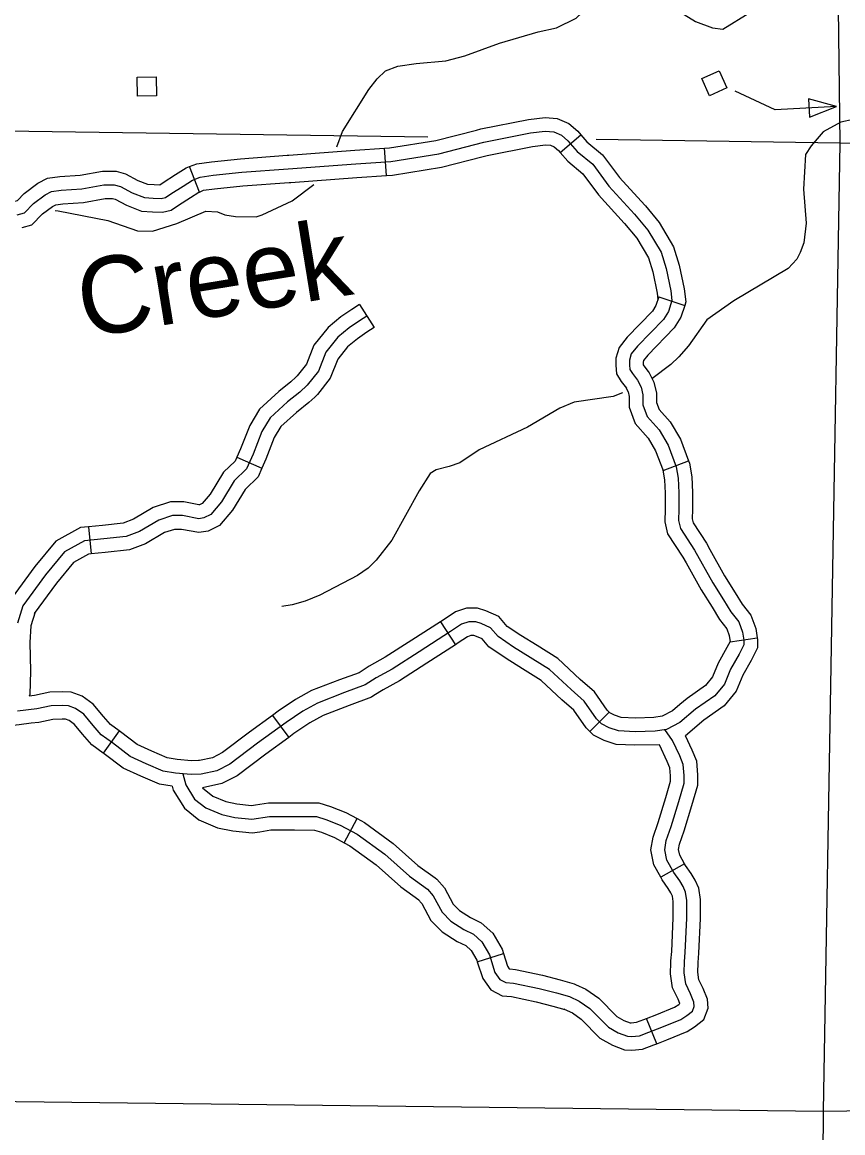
# Model space of a CAD drawing. Extents: x -19 to 366, y -4 to 359.
# Drawn here: x 137.551 to 138.405, y 195.99 to 197.146 of the extents above; entities that cross this region are included whole.
import ezdxf

# ---------------------------------------------------------------- set-up
doc = ezdxf.new("R2010")
doc.units = 0
for name, color, linetype in [('Level 35', 7, 'Continuous'), ('Level 45', 7, 'Continuous'), ('Level 5', 7, 'Continuous'), ('Level 56', 7, 'Continuous'), ('Level 60', 7, 'Continuous')]:
    doc.layers.add(name, color=color, linetype=linetype)

msp = doc.modelspace()

# ---------------------------------------------------------------- linework, layer by layer
at = {"layer": 'Level 35'}
for points in [[(137.8788, 197.0161), (137.8845, 197.0319), (137.9119, 197.0756), (137.9205, 197.0867), (137.9292, 197.095), (137.942, 197.1), (137.9613, 197.1027), (137.9919, 197.1055), (138.0119, 197.1105), (138.0478, 197.1239), (138.0882, 197.1355), (138.1071, 197.1397), (138.1275, 197.1497), (138.1399, 197.1611), (138.1452, 197.1691), (138.1534, 197.1759), (138.1716, 197.1828), (138.184, 197.184), (138.1931, 197.1814), (138.2071, 197.1746)], [(138.2071, 197.1746), (138.2253, 197.1641), (138.2401, 197.1535), (138.2519, 197.1463), (138.2693, 197.1396), (138.2803, 197.1385), (138.3084, 197.1558), (138.3345, 197.1823)], [(138.4157, 197.0444), (138.4029, 197.0416), (138.3846, 197.0314), (138.372, 197.0171), (138.3661, 197.0079), (138.3641, 196.9718), (138.367, 196.9366), (138.3643, 196.9161), (138.3607, 196.9061), (138.3571, 196.8992), (138.3482, 196.8892)], [(137.5857, 196.9496), (137.5887, 196.9492), (137.6406, 196.9392), (137.6713, 196.9286), (137.6871, 196.9283), (137.7124, 196.936), (137.7423, 196.949), (137.7544, 196.9483), (137.7623, 196.9453), (137.7733, 196.9435), (137.7948, 196.9432), (137.8009, 196.9451), (137.8322, 196.9596), (137.8546, 196.9767)], [(138.3482, 196.8892), (138.2918, 196.8558), (138.2636, 196.8358), (138.2445, 196.809), (138.2346, 196.7973), (138.2262, 196.7893), (138.2065, 196.7747)], [(138.1757, 196.7601), (138.1661, 196.756), (138.1254, 196.7503), (138.1108, 196.744), (138.0771, 196.7241), (138.0269, 196.7008), (138.0067, 196.6872), (137.9955, 196.6832), (137.9819, 196.68), (137.9756, 196.6761), (137.9645, 196.658), (137.936, 196.6067), (137.9197, 196.5859), (137.9112, 196.5774), (137.9003, 196.57), (137.861, 196.5496), (137.8456, 196.5433), (137.8321, 196.5393), (137.8216, 196.5376)]]:
    msp.add_lwpolyline(points, dxfattribs=at)
at = {"layer": 'Level 45'}
for p, q in [((138.111, 197.0099), (138.1326, 197.0284)), ((137.9303, 196.9861), (137.9284, 197.0145)), ((137.7357, 196.9689), (137.7253, 196.9954)), ((138.2135, 196.8597), (138.2405, 196.851)), ((137.9022, 196.8518), (137.9176, 196.8279)), ((137.7748, 196.6932), (137.8007, 196.6817)), ((138.218, 196.6791), (138.2446, 196.6891)), ((137.6205, 196.6207), (137.6231, 196.5924)), ((137.9866, 196.5217), (138.002, 196.4978)), ((138.2878, 196.5009), (138.3159, 196.5049)), ((137.8119, 196.4244), (137.8287, 196.4015)), ((138.162, 196.4276), (138.1419, 196.4075)), ((137.6522, 196.4082), (137.6355, 196.3852)), ((137.8863, 196.2919), (137.8999, 196.3169)), ((138.2404, 196.2699), (138.2156, 196.2561)), ((138.0248, 196.1679), (138.0519, 196.1765)), ((138.2116, 196.0827), (138.2009, 196.109))]:
    msp.add_line(p, q, dxfattribs=at)
for points in [[(138.0238, 197.0333), (138.0285, 197.0345), (138.0779, 197.0445), (138.0953, 197.0465), (138.1078, 197.0455), (138.1199, 197.0402), (138.1292, 197.0324), (138.1326, 197.0284)], [(137.9284, 197.0145), (137.9333, 197.0148), (137.9818, 197.0226), (138.0238, 197.0333)], [(137.5462, 196.9452), (137.5539, 196.9474), (137.563, 196.9568), (137.5753, 196.9659), (137.582, 196.9694), (137.5921, 196.9708), (137.6135, 196.9723), (137.6363, 196.9765), (137.6472, 196.9765), (137.6535, 196.9747), (137.6658, 196.968), (137.6787, 196.9631), (137.6878, 196.9624), (137.6959, 196.9621), (137.7005, 196.9631), (137.7061, 196.967), (137.7187, 196.9751), (137.7285, 196.9814), (137.7366, 196.9845), (137.7499, 196.9863), (137.7797, 196.9894), (137.828, 196.9929), (137.8985, 196.9982), (137.935, 197.0007), (137.9847, 197.0087), (138.0317, 197.0207), (138.0801, 197.0305), (138.0955, 197.0322), (138.1043, 197.0315), (138.1123, 197.028), (138.1191, 197.0223), (138.1288, 197.0111), (138.1449, 196.9978), (138.1617, 196.9749), (138.1882, 196.946), (138.2023, 196.9291), (138.2159, 196.9062), (138.2212, 196.8893), (138.226, 196.866), (138.2272, 196.8559), (138.2236, 196.8447), (138.2184, 196.8362), (138.1914, 196.8085), (138.185, 196.8005), (138.183, 196.794), (138.183, 196.7892)], [(138.1326, 197.0284), (138.1388, 197.0212), (138.1552, 197.0076), (138.1727, 196.9839), (138.1989, 196.9553), (138.1997, 196.9544)], [(137.8286, 197.0072), (137.8975, 197.0124), (137.9284, 197.0145)], [(138.0308, 197.0058), (138.0349, 197.0068), (138.0823, 197.0164), (138.0957, 197.018), (138.1008, 197.0176), (138.1048, 197.0158), (138.1091, 197.0122), (138.111, 197.0099)], [(138.111, 197.0099), (138.1188, 197.0009), (138.1345, 196.988), (138.1507, 196.9659), (138.1775, 196.9366), (138.1778, 196.9363)], [(137.7253, 196.9954), (137.733, 196.9984), (137.7482, 197.0004), (137.7784, 197.0036), (137.827, 197.0071), (137.8286, 197.0072)], [(137.9303, 196.9861), (137.9366, 196.9865), (137.9876, 196.9948), (138.0308, 197.0058)], [(137.5439, 196.9593), (137.5464, 196.96), (137.5536, 196.9675), (137.5677, 196.978), (137.5776, 196.9832), (137.5907, 196.985), (137.6118, 196.9864), (137.635, 196.9907), (137.639, 196.9907)], [(137.639, 196.9907), (137.6491, 196.9907), (137.6588, 196.988), (137.6717, 196.981), (137.6818, 196.9771), (137.6887, 196.9766), (137.6946, 196.9764), (137.6946, 196.9764), (137.6982, 196.9788), (137.711, 196.987), (137.722, 196.9941), (137.7253, 196.9954)], [(137.7357, 196.9689), (137.7401, 196.9707), (137.7516, 196.9722), (137.7809, 196.9753), (137.8291, 196.9788), (137.8307, 196.9789)], [(137.8307, 196.9789), (137.8995, 196.984), (137.9303, 196.9861)], [(137.639, 196.9623), (137.6452, 196.9623), (137.6481, 196.9615), (137.6598, 196.9551), (137.6756, 196.9491), (137.687, 196.9483), (137.6972, 196.9478), (137.7063, 196.9499), (137.7139, 196.9552), (137.7264, 196.9631), (137.735, 196.9687), (137.7357, 196.9689)], [(137.5514, 196.9319), (137.5615, 196.9347), (137.5725, 196.9461), (137.5829, 196.9539), (137.5864, 196.9557), (137.5936, 196.9567), (137.6153, 196.9581), (137.6376, 196.9623), (137.639, 196.9623)], [(138.1997, 196.9544), (138.2139, 196.9373), (138.229, 196.912), (138.2349, 196.8928), (138.24, 196.8683), (138.2417, 196.8545), (138.2405, 196.851)], [(138.1778, 196.9363), (138.1907, 196.9208), (138.2029, 196.9003), (138.2074, 196.8857), (138.212, 196.8637), (138.2127, 196.8573), (138.2135, 196.8597)], [(138.2135, 196.8597), (138.2106, 196.8507), (138.2071, 196.845), (138.1808, 196.8179), (138.1723, 196.8073), (138.1688, 196.7962), (138.1688, 196.7886), (138.1695, 196.7797), (138.1746, 196.7718), (138.1799, 196.7648)], [(137.9022, 196.8518), (137.8942, 196.8466), (137.883, 196.8389), (137.8695, 196.8279), (137.8548, 196.8095), (137.847, 196.7897), (137.8375, 196.7775), (137.8362, 196.7763)], [(138.2405, 196.851), (138.2366, 196.8387), (138.2296, 196.8275), (138.2021, 196.7991), (138.1978, 196.7937), (138.1972, 196.7919), (138.1972, 196.7898), (138.1973, 196.7891), (138.1979, 196.7881), (138.2025, 196.782)], [(137.9099, 196.8399), (137.9021, 196.8348), (137.8916, 196.8275), (137.8796, 196.8179), (137.8673, 196.8023), (137.8595, 196.7826), (137.848, 196.7679), (137.8402, 196.7605), (137.8274, 196.7505), (137.8095, 196.7339), (137.8008, 196.7197), (137.7917, 196.6963), (137.7848, 196.6808), (137.772, 196.6684), (137.7587, 196.6464), (137.7477, 196.6335), (137.7403, 196.6299), (137.7353, 196.6289), (137.7183, 196.6322), (137.7078, 196.6322), (137.6936, 196.6276), (137.6734, 196.6156), (137.6597, 196.6106), (137.6363, 196.6079), (137.6161, 196.606), (137.5955, 196.5946), (137.5758, 196.5707), (137.552, 196.5382), (137.5465, 196.5203)], [(137.9176, 196.8279), (137.91, 196.823), (137.9001, 196.8161), (137.8898, 196.8078), (137.8797, 196.7951), (137.8719, 196.7754), (137.8586, 196.7583), (137.8557, 196.7556)], [(138.183, 196.7892), (138.1834, 196.7844), (138.1862, 196.78), (138.1914, 196.7731), (138.1951, 196.7659), (138.1971, 196.7579), (138.1971, 196.7474), (138.2015, 196.7354), (138.2139, 196.7213), (138.2232, 196.7056), (138.2316, 196.6831), (138.2336, 196.6711), (138.2344, 196.6558), (138.2344, 196.6389), (138.234, 196.6273), (138.236, 196.6188), (138.2509, 196.5963), (138.2698, 196.5622), (138.281, 196.5445), (138.2886, 196.532), (138.2967, 196.5216), (138.3007, 196.5111), (138.3019, 196.5027), (138.3019, 196.4979), (138.2971, 196.4882), (138.2882, 196.4725), (138.2818, 196.4569), (138.2718, 196.4448), (138.2517, 196.4307), (138.2356, 196.4171), (138.2216, 196.4098), (138.2099, 196.4078), (138.189, 196.4074), (138.1718, 196.4082), (138.1621, 196.4114), (138.1541, 196.4155), (138.1489, 196.4207), (138.136, 196.4392), (138.1224, 196.4512), (138.0999, 196.4721), (138.0625, 196.4954), (138.0464, 196.5063), (138.0384, 196.5155), (138.0288, 196.52), (138.0231, 196.5216), (138.0159, 196.5216), (138.0083, 196.5192), (137.997, 196.5115), (137.9645, 196.4906), (137.9364, 196.4725), (137.9195, 196.4633), (137.9083, 196.4561), (137.8866, 196.448), (137.8585, 196.4372), (137.8432, 196.4287), (137.8259, 196.4171), (137.7962, 196.3954), (137.7673, 196.3737), (137.754, 196.3668), (137.7376, 196.3632), (137.7271, 196.3628), (137.7107, 196.3644), (137.6982, 196.3664), (137.6805, 196.3741), (137.6637, 196.3817), (137.6452, 196.3958), (137.6335, 196.4042), (137.6251, 196.4139), (137.6155, 196.4255), (137.607, 196.4315), (137.5994, 196.4344), (137.5934, 196.4348), (137.5817, 196.4344), (137.5665, 196.4311), (137.5464, 196.4287)], [(138.2025, 196.782), (138.2035, 196.7807), (138.2085, 196.7709), (138.2113, 196.7596), (138.2113, 196.7499), (138.2139, 196.7428), (138.2255, 196.7297), (138.236, 196.7118), (138.2446, 196.6891)], [(137.8362, 196.7763), (137.831, 196.7713), (137.8182, 196.7613), (137.7984, 196.743), (137.7881, 196.7261), (137.7785, 196.7018), (137.7748, 196.6932)], [(137.8557, 196.7556), (137.8495, 196.7498), (137.8366, 196.7396), (137.8206, 196.7249), (137.8136, 196.7134), (137.8048, 196.6909), (137.8007, 196.6817)], [(138.1793, 196.7656), (138.1817, 196.761), (138.1829, 196.7561), (138.1829, 196.7449), (138.1891, 196.728), (138.2024, 196.7129), (138.2103, 196.6995), (138.218, 196.6791)], [(137.7748, 196.6932), (137.7729, 196.689), (137.7608, 196.6773), (137.7471, 196.6547), (137.7387, 196.6449), (137.7358, 196.6435), (137.7353, 196.6434), (137.7197, 196.6464), (137.7167, 196.6464)], [(138.2446, 196.6891), (138.2454, 196.6868), (138.2478, 196.6726), (138.2486, 196.6562), (138.2486, 196.6387), (138.2483, 196.6287), (138.2493, 196.6246), (138.2631, 196.6037), (138.2668, 196.5968)], [(137.8007, 196.6817), (137.7967, 196.6725), (137.7832, 196.6594), (137.7702, 196.638), (137.7566, 196.6221), (137.7449, 196.6162), (137.7352, 196.6145), (137.717, 196.6179), (137.7167, 196.6179)], [(138.2178, 196.6794), (138.2195, 196.6695), (138.2202, 196.6554), (138.2202, 196.6392), (138.2198, 196.6258), (138.2228, 196.6131), (138.2387, 196.589), (138.242, 196.5831)], [(137.7167, 196.6464), (137.7056, 196.6464), (137.6877, 196.6406), (137.6673, 196.6285), (137.6564, 196.6245), (137.6348, 196.622), (137.6205, 196.6207)], [(137.6205, 196.6207), (137.6119, 196.6199), (137.5863, 196.6057), (137.5646, 196.5794), (137.5409, 196.547)], [(137.7167, 196.6179), (137.71, 196.6179), (137.6995, 196.6145), (137.6795, 196.6028), (137.663, 196.5967), (137.6378, 196.5937), (137.6231, 196.5924)], [(138.2668, 196.5968), (138.282, 196.5694), (138.2931, 196.552), (138.3004, 196.5401), (138.3092, 196.5286), (138.3145, 196.5147), (138.3159, 196.5049)], [(137.6231, 196.5924), (137.6204, 196.5921), (137.6048, 196.5834), (137.587, 196.562), (137.5638, 196.5302)], [(138.242, 196.5831), (138.2575, 196.5549), (138.269, 196.5369), (138.2769, 196.524), (138.2842, 196.5145), (138.2869, 196.5075), (138.2878, 196.5009)], [(137.5649, 196.5317), (137.5605, 196.5177), (137.5593, 196.5003), (137.5602, 196.4702), (137.5592, 196.446), (137.5588, 196.4445)], [(138.0869, 196.497), (138.0702, 196.5074), (138.0559, 196.517), (138.0471, 196.5272), (138.0337, 196.5333), (138.0251, 196.5358), (138.0137, 196.5358), (138.002, 196.5321), (137.9892, 196.5234), (137.9866, 196.5217)], [(137.9866, 196.5217), (137.9568, 196.5026), (137.9291, 196.4848), (137.9123, 196.4755), (137.9018, 196.4688)], [(138.0718, 196.4729), (138.0548, 196.4835), (138.0369, 196.4956), (138.0297, 196.5039), (138.0238, 196.5066), (138.0212, 196.5074), (138.0181, 196.5074), (138.0145, 196.5062), (138.0049, 196.4997), (138.002, 196.4978)], [(138.2877, 196.5017), (138.2877, 196.5012), (138.2845, 196.4949), (138.2754, 196.4787), (138.2695, 196.4643), (138.2621, 196.4554), (138.243, 196.442), (138.2356, 196.4357)], [(138.3159, 196.5049), (138.3161, 196.5037), (138.3161, 196.4945), (138.3096, 196.4815), (138.3011, 196.4663), (138.2941, 196.4494), (138.2815, 196.4343), (138.2604, 196.4195), (138.2412, 196.4031)], [(138.002, 196.4978), (137.9722, 196.4787), (137.9437, 196.4603), (137.9268, 196.4511), (137.9172, 196.4449)], [(138.162, 196.4276), (138.1598, 196.4298), (138.1467, 196.4487), (138.1319, 196.4618), (138.1085, 196.4835), (138.0869, 196.497)], [(137.9019, 196.4688), (137.8816, 196.4613), (137.8524, 196.4501), (137.8358, 196.4409), (137.8178, 196.4287), (137.8119, 196.4244)], [(138.1419, 196.4075), (138.1379, 196.4115), (138.1253, 196.4297), (138.1128, 196.4407), (138.0912, 196.4608), (138.0718, 196.4729)], [(137.6522, 196.4082), (137.6432, 196.4148), (137.6359, 196.4231), (137.6252, 196.436), (137.6137, 196.4442), (137.6024, 196.4484), (137.5936, 196.449), (137.58, 196.4485), (137.5641, 196.4452), (137.5588, 196.4445)], [(137.9172, 196.4449), (137.9147, 196.4433), (137.8916, 196.4347), (137.8645, 196.4243), (137.8506, 196.4166), (137.8341, 196.4054), (137.8287, 196.4015)], [(138.2356, 196.4357), (138.2277, 196.429), (138.217, 196.4235), (138.2086, 196.422), (138.1892, 196.4216), (138.1744, 196.4223), (138.1676, 196.4246), (138.1625, 196.4271), (138.162, 196.4276)], [(137.6355, 196.3852), (137.6239, 196.3937), (137.6143, 196.4047), (137.6057, 196.415), (137.6003, 196.4189), (137.5964, 196.4203), (137.5931, 196.4205), (137.5834, 196.4202), (137.5688, 196.4171), (137.5607, 196.4161)], [(137.8119, 196.4244), (137.7878, 196.4068), (137.7597, 196.3857), (137.7492, 196.3803), (137.7358, 196.3774), (137.7348, 196.3773)], [(137.5607, 196.4161), (137.5481, 196.4146), (137.521, 196.4113), (137.5031, 196.4105), (137.491, 196.4088), (137.4869, 196.4074), (137.4715, 196.3969)], [(137.7186, 196.3637), (137.7215, 196.3521), (137.7308, 196.3373), (137.7424, 196.328), (137.7589, 196.3211), (137.7725, 196.3182), (137.7902, 196.3164), (137.8088, 196.3193), (137.8348, 196.3193), (137.8577, 196.319), (137.8673, 196.3161), (137.8821, 196.3103), (137.8998, 196.3008), (137.9285, 196.2799), (137.9542, 196.257), (137.9731, 196.2434), (137.9789, 196.2367), (137.9881, 196.2196), (137.9971, 196.2103), (138.0107, 196.2016), (138.0209, 196.1967), (138.0296, 196.1888), (138.0374, 196.1752), (138.0432, 196.157), (138.0484, 196.1497), (138.0545, 196.1465), (138.0623, 196.1459), (138.0893, 196.1401), (138.1072, 196.1355), (138.1206, 196.1317), (138.1307, 196.1271), (138.142, 196.1193), (138.1611, 196.0998), (138.1713, 196.094), (138.1809, 196.0906), (138.1852, 196.0903), (138.1936, 196.0911), (138.2032, 196.0946), (138.2168, 196.1001), (138.2365, 196.108), (138.2426, 196.112), (138.2487, 196.1167), (138.2504, 196.1216), (138.2501, 196.1259), (138.2466, 196.1346), (138.2417, 196.1451), (138.24, 196.1564), (138.2403, 196.1683), (138.2411, 196.1778), (138.2429, 196.2135), (138.2429, 196.2318), (138.2414, 196.2405), (138.2388, 196.2463), (138.2353, 196.2521), (138.2292, 196.2608), (138.222, 196.2738), (138.2197, 196.2845), (138.2214, 196.2941), (138.2263, 196.3086), (138.2345, 196.3347), (138.24, 196.3538), (138.24, 196.3619), (138.2391, 196.3733), (138.2353, 196.3822), (138.2278, 196.3982), (138.22, 196.4096)], [(137.7348, 196.3773), (137.7275, 196.3771), (137.7125, 196.3785), (137.7022, 196.3802), (137.6863, 196.3871), (137.671, 196.394), (137.6537, 196.4072), (137.6522, 196.4082)], [(137.8287, 196.4015), (137.8047, 196.384), (137.7749, 196.3616), (137.7589, 196.3534), (137.739, 196.349)], [(138.2142, 196.3937), (138.1888, 196.3932), (138.1691, 196.3941), (138.1567, 196.3983), (138.1457, 196.4038), (138.1419, 196.4075)], [(138.2542, 196.3582), (138.2542, 196.3625), (138.2531, 196.3766), (138.2483, 196.388), (138.2412, 196.4031)], [(138.2258, 196.3582), (138.2258, 196.3614), (138.2251, 196.3699), (138.2224, 196.3765), (138.2142, 196.3937)], [(137.7073, 196.3506), (137.6942, 196.3527), (137.6748, 196.3611), (137.6563, 196.3694), (137.6367, 196.3844), (137.6355, 196.3852)], [(138.2156, 196.2561), (138.2086, 196.2687), (138.2052, 196.2843), (138.2076, 196.2977), (138.2128, 196.313), (138.2209, 196.3388), (138.2258, 196.3558), (138.2258, 196.3582)], [(138.2404, 196.2699), (138.2354, 196.2789), (138.2342, 196.2848), (138.2352, 196.2905), (138.2399, 196.3042), (138.2481, 196.3306), (138.2542, 196.3518), (138.2542, 196.3582)], [(137.7073, 196.3506), (137.7083, 196.3464), (137.7201, 196.3277), (137.7351, 196.3157), (137.7547, 196.3075), (137.7704, 196.3041), (137.7906, 196.3021), (137.7985, 196.3033)], [(137.739, 196.349), (137.7497, 196.3403), (137.7632, 196.3347), (137.7747, 196.3322), (137.7898, 196.3307), (137.7941, 196.3314)], [(137.7941, 196.3314), (137.8077, 196.3335), (137.8349, 196.3335), (137.8599, 196.3332), (137.872, 196.3296), (137.8881, 196.3232), (137.8999, 196.3169)], [(137.8999, 196.3169), (137.9074, 196.3128), (137.9374, 196.291), (137.9631, 196.2681), (137.9808, 196.2553)], [(137.7985, 196.3033), (137.8099, 196.3051), (137.8348, 196.3051), (137.8555, 196.3049), (137.8626, 196.3027), (137.8761, 196.2974), (137.8863, 196.2919)], [(137.8863, 196.2919), (137.8922, 196.2887), (137.9195, 196.2688), (137.9453, 196.2459), (137.9641, 196.2323)], [(138.2544, 196.1666), (138.2544, 196.1674), (138.2553, 196.1768), (138.2571, 196.2131), (138.2571, 196.2329), (138.2551, 196.2446), (138.2514, 196.2528), (138.2473, 196.2598), (138.2413, 196.2683), (138.2404, 196.2699)], [(137.9808, 196.2553), (137.9827, 196.2539), (137.9906, 196.2448), (137.9997, 196.2281), (138.0062, 196.2214), (138.0177, 196.214), (138.0289, 196.2086), (138.0408, 196.1979), (138.0505, 196.181), (138.0519, 196.1765)], [(138.226, 196.1673), (138.2261, 196.1691), (138.227, 196.1788), (138.2287, 196.2138), (138.2287, 196.2306), (138.2277, 196.2363), (138.2262, 196.2397), (138.2234, 196.2443), (138.2172, 196.2532), (138.2156, 196.2561)], [(137.9634, 196.2328), (137.9671, 196.2286), (137.9766, 196.2111), (137.9881, 196.1992), (138.0038, 196.1892), (138.0129, 196.1848), (138.0184, 196.1798), (138.0243, 196.1695), (138.0248, 196.1679)], [(138.0248, 196.1679), (138.0304, 196.1505), (138.0389, 196.1387), (138.0505, 196.1326), (138.0603, 196.1318), (138.086, 196.1263), (138.1035, 196.1218), (138.1157, 196.1184), (138.115, 196.1187)], [(138.0519, 196.1765), (138.0561, 196.1634), (138.058, 196.1607), (138.0585, 196.1605), (138.0644, 196.16), (138.0926, 196.154), (138.111, 196.1492), (138.1255, 196.1451), (138.1268, 196.1445)], [(138.2009, 196.109), (138.2115, 196.1133), (138.2299, 196.1206), (138.2343, 196.1236), (138.2354, 196.1244), (138.2336, 196.129), (138.228, 196.1409), (138.2257, 196.1555), (138.226, 196.1673)], [(138.2116, 196.0827), (138.2221, 196.0869), (138.2431, 196.0953), (138.2508, 196.1004), (138.2606, 196.1079), (138.2648, 196.1196), (138.2641, 196.1291), (138.2597, 196.1403), (138.2554, 196.1493), (138.2542, 196.1573), (138.2544, 196.1666)], [(138.1268, 196.1445), (138.1378, 196.1395), (138.1512, 196.1302), (138.1699, 196.1112), (138.1773, 196.107), (138.1838, 196.1046), (138.1849, 196.1045), (138.1904, 196.1051), (138.1981, 196.1079), (138.2009, 196.109)], [(138.115, 196.1187), (138.1237, 196.1147), (138.1328, 196.1083), (138.1524, 196.0885), (138.1653, 196.0811), (138.1779, 196.0765), (138.1855, 196.076), (138.1968, 196.0772), (138.2083, 196.0814), (138.2116, 196.0827)]]:
    msp.add_lwpolyline(points, dxfattribs=at)
at = {"layer": 'Level 5'}
for points in [[(138.3957, 197.5258), (138.4019, 197.0199)], [(137.9733, 197.0259), (137.4112, 197.0338)], [(138.4019, 197.0199), (138.1483, 197.0235)], [(138.4019, 197.0199), (138.3846, 196.0125)], [(139.3505, 197.0167), (138.6455, 197.0187), (138.4019, 197.0199)], [(137.4003, 196.0243), (138.3846, 196.0125)], [(138.3846, 196.0125), (139.3757, 196.0263)], [(138.3846, 196.0125), (138.382, 195.6858), (138.3914, 195.0138)]]:
    msp.add_lwpolyline(points, dxfattribs=at)
at = {"layer": 'Level 56'}
for points in [[(138.2763, 197.0951), (138.2845, 197.0772), (138.2664, 197.069), (138.2583, 197.087)], [(137.6714, 197.0687), (137.6711, 197.0884), (137.6908, 197.0887), (137.6912, 197.069)], [(138.3692, 197.066), (138.3702, 197.0467), (138.3986, 197.0579)]]:
    msp.add_lwpolyline(points, close=True, dxfattribs=at)
msp.add_lwpolyline([(138.3986, 197.0579), (138.3345, 197.0545), (138.2932, 197.0739)], dxfattribs=at)
at = {"layer": 'Level 60'}
for points in [[(146.7783, 1.697), (146.5788, 10.3131), (146.3785, 18.9294), (146.1776, 27.5458), (145.9759, 36.1624), (145.7736, 44.7791), (145.5705, 53.396), (145.3668, 62.013), (145.1624, 70.6301), (144.9572, 79.2474), (144.7514, 87.8648), (144.5449, 96.4823), (144.3377, 105.1), (144.1299, 113.7179), (143.9213, 122.3359), (143.712, 130.954), (143.5021, 139.5723), (143.2915, 148.1907), (143.0802, 156.8092), (142.8682, 165.4279), (142.6555, 174.0468), (142.4422, 182.6658), (142.2282, 191.2849), (142.0135, 199.9042), (141.7981, 208.5236), (141.582, 217.1432), (141.3653, 225.7629), (141.1479, 234.3828), (140.9298, 243.0028), (140.711, 251.623), (140.4916, 260.2433), (140.2715, 268.8638), (140.0508, 277.4844), (139.8293, 286.1051), (139.6072, 294.726), (139.3845, 303.3471), (139.161, 311.9683), (138.937, 320.5896), (138.7122, 329.2111), (138.4868, 337.8328), (138.2607, 346.4546)], [(139.4406, 1.5315), (139.2511, 10.1473), (139.0608, 18.7633), (138.8699, 27.3793), (138.6784, 35.9956), (138.4861, 44.6119), (138.2932, 53.2285), (138.0997, 61.8451), (137.9055, 70.4619), (137.7106, 79.0789), (137.5151, 87.6959), (137.319, 96.3132), (137.1221, 104.9306), (136.9247, 113.5481), (136.7265, 122.1658), (136.5278, 130.7836), (136.3283, 139.4016), (136.1282, 148.0197), (135.9275, 156.6379), (135.7261, 165.2564), (135.5241, 173.8749), (135.3214, 182.4936), (135.1181, 191.1125), (134.9141, 199.7315), (134.7095, 208.3506), (134.5043, 216.9699), (134.2984, 225.5894), (134.0919, 234.209), (133.8847, 242.8288), (133.6769, 251.4487), (133.4685, 260.0687), (133.2594, 268.6889), (133.0497, 277.3093), (132.8393, 285.9298), (132.6283, 294.5504), (132.4167, 303.1713), (132.2044, 311.7922), (131.9916, 320.4133), (131.778, 329.0346), (131.5639, 337.656), (131.3491, 346.2776)], [(0, 189.5162), (7.1121, 189.5206), (14.2243, 189.5339), (21.3364, 189.556), (28.4484, 189.5869), (35.5605, 189.6267), (42.6725, 189.6754), (49.7844, 189.7329), (56.8962, 189.7992), (64.0079, 189.8744), (71.1196, 189.9584), (78.2311, 190.0512), (85.3425, 190.1529), (92.4538, 190.2635), (99.5649, 190.3829), (106.6759, 190.5111), (113.7867, 190.6482), (120.8974, 190.7941), (128.0078, 190.9489), (135.1181, 191.1125), (142.2282, 191.2849), (149.338, 191.4662), (156.4476, 191.6563), (163.5569, 191.8553), (170.666, 192.0631), (177.7749, 192.2798), (184.8835, 192.5053), (191.9917, 192.7396), (199.0997, 192.9828), (206.2074, 193.2348), (213.3147, 193.4956), (220.4218, 193.7653), (227.5285, 194.0438), (234.6348, 194.3312), (241.7408, 194.6274), (248.8464, 194.9324), (255.9516, 195.2463), (263.0564, 195.569), (270.1608, 195.9005), (277.2648, 196.2409), (284.3683, 196.5901), (291.4715, 196.9481), (298.5741, 197.315), (305.6763, 197.6907), (312.7781, 198.0753), (319.8793, 198.4686), (326.9801, 198.8708), (334.0804, 199.2818), (341.1801, 199.7017)]]:
    msp.add_spline(points, degree=3, dxfattribs=at)

# ---------------------------------------------------------------- texts
at = {"layer": 'Level 35'}
msp.add_text('Creek', height=0.08, rotation=9.236, dxfattribs=at).set_placement((137.6157, 196.8168))

doc.saveas('drawing.dxf')
